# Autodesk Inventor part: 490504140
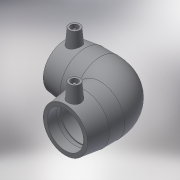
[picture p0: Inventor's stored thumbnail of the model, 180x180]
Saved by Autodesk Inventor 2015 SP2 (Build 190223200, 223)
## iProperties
Created: 2017-06
Part Number: 490504140
Material: Generic
Description: PLASSON 90° ELBOW 140
Document SubType Name: Modeling
Designer: KIM
Mass: 55.0731 g
Surface Area: 148.067 cm^2
Volume: 55.0731 cm^3
Density: 1 g/cm^3
Appearance: Default
Author: KIM
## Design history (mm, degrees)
derived "490504.ipt"
feature "Solid1::490504.ipt"
tag "TaggingFeature1"
body "Solid1"
other parameters: "d2" = 183, "d4" = 77.25, "d5" = 164.7, "d8" = 168 deg, "d10" = 37.2, "d11" = 12.4, "d14" = 17.6296, "d19" = 3.52592, "d20" = 168 deg, "d22" = 168.36, "d23" = 183, "d24" = 163.3092, "d29" = 94, "d30" = 15, "d31" = 108.15, "d34" = 5 deg, "d35" = 15, "d39" = 5 deg, "d41" = 4, "d42" = 14, "d43" = 0, "d45" = 4, "d46" = 14, "d47" = 0, "d50" = 119, "d51" = 37.2, "d52" = 93, "d54" = 90 deg, "d67" = 45 deg, "d71" = 90 deg, "d75" = 9.15, "d82" = 45 deg, "d83" = 93, "d84" = 164.7, "d86" = 82.35, "d87" = 90 deg, "d90" = 93, "d91" = 0, "d92" = 93, "d93" = 0, "d94" = 90 deg, "d95" = 84.18, "d98" = 309, "d101" = 3, "d102" = 0, "d103" = 3, "d104" = 0, "d105" = 26.97, "d106" = 6.7425, "d107" = 309, "d110" = 51.15, "L_" = 309, "L_1" = 93, "D_" = 183, "A_" = 94, "d_2" = 12
